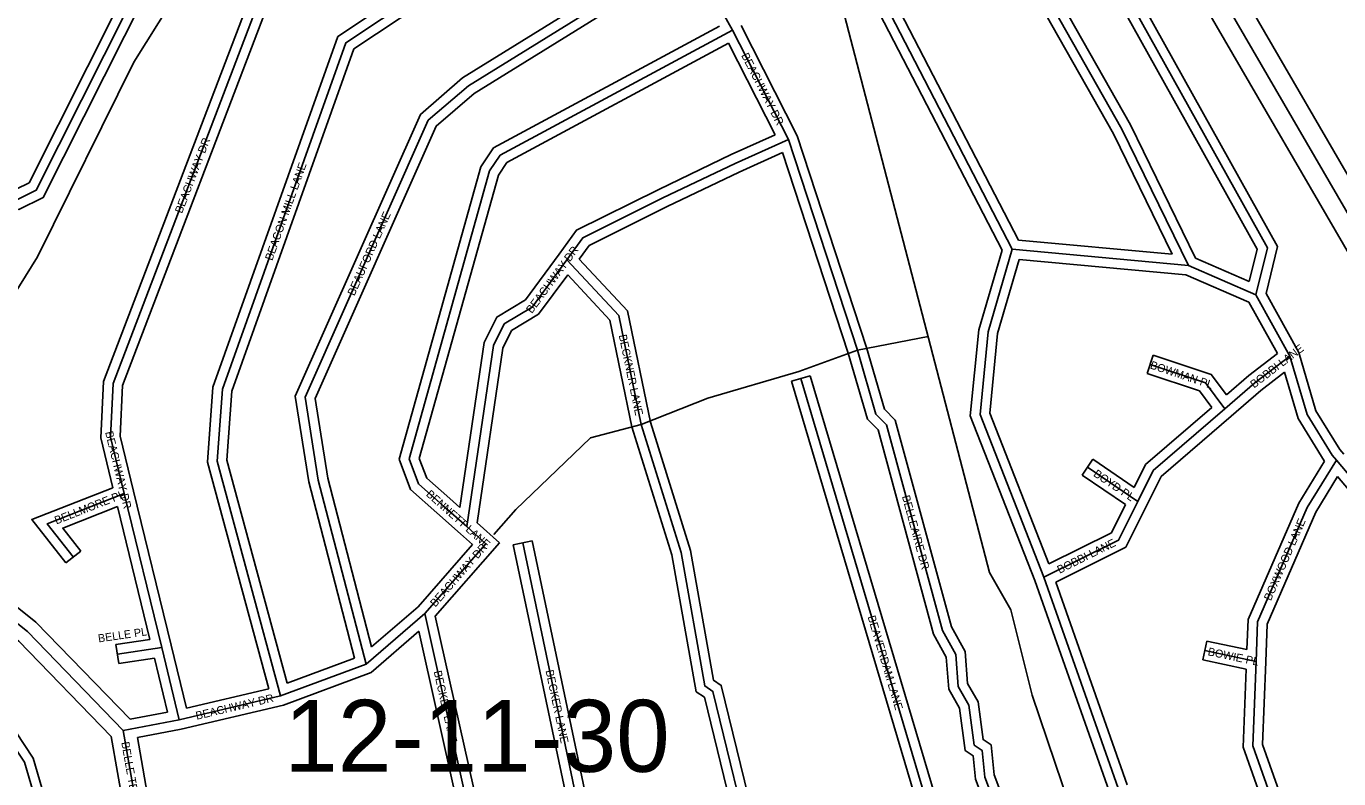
# Model space of a CAD drawing. Extents: x 457167 to 656239, y 1787309 to 1969297.
# Drawn here: x 580059 to 584161, y 1900258 to 1902611 of the extents above; entities that cross this region are included whole.
import ezdxf

# ---------------------------------------------------------------- set-up
doc = ezdxf.new("R2010")
doc.units = 0
for name, color, linetype in [('Level 13', 7, 'Continuous'), ('Level 14', 7, 'Continuous'), ('Level 2', 7, 'Continuous'), ('Level 22', 7, 'Continuous'), ('Level 23', 7, 'Continuous'), ('Level 31', 7, 'Continuous'), ('Level 32', 7, 'Continuous'), ('Level 34', 7, 'Continuous'), ('Level 5', 7, 'Continuous')]:
    doc.layers.add(name, color=color, linetype=linetype)

msp = doc.modelspace()

# ---------------------------------------------------------------- linework, layer by layer
at = {"layer": 'Level 13'}
msp.add_line((584688.869, 1901162.621), (582396.2, 1905115.545), dxfattribs=at)
at = {"layer": 'Level 14'}
for p, q in [((584740.772, 1901192.724), (582448.103, 1905145.647)), ((584636.968, 1901132.518), (582344.298, 1905085.441))]:
    msp.add_line(p, q, dxfattribs=at)
at = {"layer": 'Level 22'}
msp.add_line((580428.56, 1900033.995), (580362.242, 1900409.045), dxfattribs=at)
msp.add_lwpolyline([(580362.242, 1900409.045), (580062.744, 1900718.027), (579859.602, 1900880.267)], dxfattribs=at)
at = {"layer": 'Level 23'}
for p, q in [((580389.425, 1900025.596), (580324.989, 1900390.006)), ((580462.804, 1900070.058), (580406.775, 1900386.923))]:
    msp.add_line(p, q, dxfattribs=at)
for points in [[(580384.317, 1900443.743), (580089.695, 1900747.696), (579884.564, 1900911.523)], [(580324.988, 1900390.006), (580035.794, 1900688.359), (579859.518, 1900829.141)]]:
    msp.add_lwpolyline(points, dxfattribs=at)
at = {"layer": 'Level 31'}
for p, q in [((582266.575, 1902598.675), (582125.284, 1902848.78)), ((582441.067, 1902256.503), (582266.575, 1902598.675)), ((582274.33, 1902181.926), (582441.067, 1902256.503)), ((582656.583, 1901597.52), (582441.067, 1902256.503)), ((582049.027, 1902073.649), (582274.33, 1902181.926)), ((583690.989, 1901862.755), (583140.767, 1901913.656)), ((581639.815, 1901732.647), (581748.524, 1901880.431)), ((583901.593, 1901771.068), (583690.989, 1901862.755)), ((584008.041, 1901578.858), (583901.593, 1901771.068)), ((583898.831, 1901495.433), (584008.041, 1901578.858)), ((583003.924, 1899746.261), (582479.959, 1901509.025)), ((583805.204, 1901414.161), (583898.831, 1901495.433)), ((583533.447, 1901124.871), (583375.647, 1901232.093)), ((584153.338, 1901253.479), (584374.743, 1900990.5)), ((580482.631, 1900668.074), (580365.343, 1901149.412)), ((581362.606, 1901111.381), (581435.916, 1901046.141)), ((581435.916, 1901046.141), (581495.897, 1900992.564)), ((581305.019, 1900774.401), (581495.897, 1900992.564)), ((581820.42, 1899998.442), (581610.676, 1900995.606)), ((583471.604, 1900228.981), (583239.216, 1900887.993)), ((581121.252, 1900616.226), (581305.019, 1900774.401)), ((580482.631, 1900668.074), (580343.971, 1900647.631)), ((580537.49, 1900442.141), (580482.631, 1900668.074)), ((583902.542, 1900624.869), (583742.37, 1900658.637)), ((580854.304, 1900516.767), (581121.252, 1900616.226)), ((580537.49, 1900442.141), (580854.304, 1900516.767)), ((580362.242, 1900409.045), (580537.49, 1900442.141))]:
    msp.add_line(p, q, dxfattribs=at)
for points in [[(582335.899, 1904365.836), (582514.45, 1904471.299), (583937.804, 1901917.545), (583901.593, 1901771.068)], [(583690.989, 1901862.755), (583483.265, 1902288.259), (582826.513, 1903448.117), (582477.519, 1904123.731)], [(583140.767, 1901913.656), (582151.709, 1903824.377), (582151.791, 1903865.832)], [(579794.104, 1902114.238), (580031.815, 1902069.383), (580090.372, 1902097.991), (580656.652, 1903224.119)], [(580854.304, 1900516.767), (580655.499, 1901250.638), (580672.489, 1901475.697), (581057.78, 1902558.929), (581958.997, 1903157.481)], [(581121.252, 1900616.226), (580972.036, 1901191.811), (580930.911, 1901450.443), (581315.758, 1902316.583), (581440.917, 1902424.696), (582125.284, 1902848.78)], [(580330.754, 1901493.124), (580816.27, 1902767.786), (580867.57, 1902824.774)], [(581255.761, 1901258.145), (581507.144, 1902158.012), (581540.624, 1902207.763), (582266.575, 1902598.675)], [(581748.524, 1901880.431), (581798.574, 1901949.059), (582049.027, 1902073.649)], [(583239.216, 1900887.993), (583039.923, 1901396.756), (583065.229, 1901655.256), (583140.767, 1901913.656)], [(581981.167, 1901365.411), (581910.633, 1901706.284), (581748.524, 1901880.431)], [(581435.916, 1901046.141), (581519.718, 1901612.888), (581552.599, 1901680.096), (581639.815, 1901732.647)], [(583237.357, 1899779.255), (583054.859, 1900263.258), (583046.439, 1900346.548), (583021.673, 1900363.325), (583005.069, 1900488.451), (582971.8, 1900546.698), (582963.73, 1900646.716), (582922.23, 1900721.708), (582748.001, 1901363.881), (582714.685, 1901397.401), (582656.583, 1901597.52)], [(584008.041, 1901578.858), (584062.052, 1901396.205), (584140.015, 1901269.505), (584153.338, 1901253.479)], [(583805.204, 1901414.161), (583744.003, 1901496.101), (583571.8, 1901553.529)], [(580365.343, 1901149.412), (580322.148, 1901326.23), (580330.754, 1901493.124)], [(583533.447, 1901124.871), (583581.324, 1901221.143), (583805.204, 1901414.161)], [(582387.155, 1899763.85), (582362.437, 1899964.266), (582337.369, 1899989.043), (582204.914, 1900531.133), (582179.831, 1900547.911), (582105.63, 1900964.792), (581981.167, 1901365.411)], [(581255.761, 1901258.145), (581285.489, 1901179.901), (581362.606, 1901111.381)], [(583902.542, 1900624.869), (583907.234, 1900748.498), (584062.442, 1901105.654), (584153.338, 1901253.479)], [(580365.343, 1901149.412), (580125.114, 1901054.995), (580206.291, 1900951.191)], [(583239.216, 1900887.993), (583472.804, 1901004.262), (583533.447, 1901124.871)], [(581470.657, 1900140.603), (581429.159, 1900215.597), (581305.019, 1900774.401)], [(580543.027, 1898633.378), (580053.642, 1900309.676), (580003.879, 1900384.69), (579687.431, 1900643.528)], [(584550.874, 1899010.497), (584405.606, 1899192.962), (584071.775, 1899853.983), (583891.854, 1900360.887), (583902.542, 1900624.869)]]:
    msp.add_lwpolyline(points, dxfattribs=at)
at = {"layer": 'Level 32'}
for p, q in [((582468.855, 1902268.05), (582293.011, 1902612.874)), ((582399.999, 1902270.999), (582253.788, 1902557.714)), ((582261.706, 1902209.144), (582399.999, 1902270.999)), ((582685.254, 1901606.366), (582468.855, 1902268.049)), ((582286.955, 1902154.708), (582422.909, 1902215.516)), ((582627.914, 1901588.671), (582422.909, 1902215.516)), ((582035.665, 1902100.509), (582261.706, 1902209.144)), ((582062.389, 1902046.787), (582286.955, 1902154.708)), ((583640.623, 1901897.542), (583159.869, 1901942.016)), ((581619.2, 1901755.251), (581724.358, 1901898.208)), ((583880.995, 1901812.756), (583713.1, 1901885.849)), ((583683.431, 1901833.325), (583162.625, 1901881.504)), ((581660.431, 1901710.042), (581751.236, 1901833.486)), ((583880.284, 1901747.626), (583683.431, 1901833.325)), ((584035.879, 1901590.516), (583933.544, 1901775.3)), ((583969.251, 1901586.978), (583880.283, 1901747.626)), ((583562.309, 1901525.069), (583581.29, 1901581.989)), ((583879.874, 1901518.704), (583969.251, 1901586.978)), ((582451.203, 1901500.477), (582508.716, 1901517.573)), ((583025.317, 1899779.582), (582508.716, 1901517.573)), ((583809.919, 1901457.981), (583879.874, 1901518.704)), ((583917.789, 1901472.161), (583991.629, 1901528.566)), ((582967.102, 1899764.853), (582451.203, 1901500.477)), ((583824.869, 1901391.505), (583917.789, 1901472.161)), ((583358.787, 1901207.278), (583392.508, 1901256.906)), ((583521.887, 1901168.997), (583392.508, 1901256.906)), ((583494.826, 1901114.843), (583358.787, 1901207.278)), ((584157.139, 1901202.383), (584338.78, 1900986.633)), ((580511.779, 1900675.176), (580394.491, 1901156.514)), ((580445.692, 1900692.952), (580344.333, 1901108.918)), ((581382.55, 1901133.791), (581414.364, 1901105.48)), ((581342.663, 1901088.97), (581415.973, 1901023.729)), ((581415.931, 1901023.766), (581453.767, 1900989.971)), ((581467.96, 1901057.745), (581538.029, 1900995.156)), ((581283.839, 1900795.754), (581453.767, 1900989.971)), ((581337.599, 1900766.078), (581538.029, 1900995.156)), ((581581.319, 1900989.43), (581640.034, 1901001.78)), ((581779.45, 1900047.478), (581581.319, 1900989.43)), ((581846.52, 1900020.11), (581640.034, 1901001.78)), ((580229.923, 1900969.671), (580182.659, 1900932.709)), ((583443.464, 1900218.574), (583211.095, 1900877.53)), ((583499.747, 1900239.388), (583276.331, 1900872.954)), ((581138.202, 1900670.396), (581283.839, 1900795.754)), ((581136.756, 1900589.986), (581286.602, 1900718.966)), ((580445.692, 1900692.952), (580339.595, 1900677.311)), ((580348.348, 1900617.95), (580339.595, 1900677.311)), ((580559.614, 1900478.173), (580511.784, 1900675.153)), ((583736.182, 1900629.281), (583748.559, 1900687.992)), ((583873.914, 1900661.564), (583748.559, 1900687.992)), ((580459.935, 1900634.401), (580348.348, 1900617.95)), ((580500.884, 1900465.758), (580459.935, 1900634.401)), ((580874.659, 1900556.366), (581085.422, 1900634.891)), ((583871.541, 1900600.744), (583736.182, 1900629.281)), ((580863.016, 1900487.996), (581136.757, 1900589.986)), ((580559.614, 1900478.173), (580817.239, 1900538.858)), ((580384.316, 1900443.743), (580500.884, 1900465.758)), ((580543.717, 1900412.784), (580863.016, 1900487.996)), ((580406.775, 1900386.923), (580543.718, 1900412.785))]:
    msp.add_line(p, q, dxfattribs=at)
for points in [[(582319.358, 1904390.907), (582525.679, 1904512.774), (583969.764, 1901921.822), (583933.544, 1901775.301)], [(582376.878, 1904355.196), (582503.221, 1904429.824), (583905.842, 1901913.267), (583880.996, 1901812.756)], [(583640.623, 1901897.543), (583456.708, 1902274.274), (582800.124, 1903433.837), (582451.228, 1904109.261)], [(583713.099, 1901885.849), (583509.824, 1902302.243), (582852.902, 1903462.398), (582503.813, 1904138.197)], [(583108.6, 1901910.537), (582121.694, 1903817.101), (582121.775, 1903857.911)], [(583159.868, 1901942.016), (582181.724, 1903831.653), (582181.808, 1903873.752)], [(579788.541, 1902084.757), (580036.038, 1902038.056), (580112.63, 1902075.476), (580683.914, 1903211.55)], [(579799.665, 1902143.719), (580027.594, 1902100.71), (580068.114, 1902120.506), (580615.809, 1903209.671)], [(580817.239, 1900538.858), (580625.196, 1901247.763), (580642.876, 1901481.964), (581032.862, 1902578.394), (581919.243, 1903167.091)], [(580874.659, 1900556.366), (580685.802, 1901253.513), (580702.102, 1901469.431), (581082.699, 1902539.463), (581948.188, 1903114.286)], [(580301.039, 1901499.386), (580790.227, 1902783.697), (580845.025, 1902844.566)], [(581085.421, 1900634.891), (580942.634, 1901185.676), (580899.888, 1901454.506), (581291.067, 1902334.9), (581423.1, 1902448.949), (582085.483, 1902859.409)], [(580360.473, 1901486.86), (580842.313, 1902751.876), (580890.115, 1902804.981)], [(581138.202, 1900670.396), (581001.438, 1901197.944), (580961.934, 1901446.38), (581340.449, 1902298.267), (581458.734, 1902400.443), (582114.531, 1902806.821)], [(581224.214, 1901256.713), (581479.552, 1902170.746), (581519.874, 1902230.664), (582225.397, 1902610.573)], [(581287.311, 1901259.575), (581534.734, 1902145.278), (581561.375, 1902184.863), (582253.787, 1902557.715)], [(581724.284, 1901898.109), (581778.653, 1901972.656), (582035.665, 1902100.509)], [(581787.35, 1901882.752), (581818.495, 1901925.461), (582062.389, 1902046.787)], [(583211.095, 1900877.529), (583009.364, 1901392.516), (583035.645, 1901660.977), (583108.6, 1901910.537)], [(582010.25, 1901372.918), (581938.311, 1901720.582), (581787.35, 1901882.752)], [(583255.195, 1900929.456), (583070.481, 1901400.997), (583094.813, 1901649.536), (583162.625, 1901881.504)], [(581952.085, 1901357.902), (581882.955, 1901691.986), (581751.236, 1901833.486)], [(581414.365, 1901105.48), (581490.721, 1901621.886), (581529.538, 1901701.227), (581619.2, 1901755.251)], [(581467.959, 1901057.745), (581548.714, 1901603.89), (581575.659, 1901658.965), (581660.431, 1901710.042)], [(583278.644, 1899754.79), (583084.312, 1900270.175), (583074.876, 1900363.521), (583049.642, 1900380.614), (583034.034, 1900498.224), (583001.166, 1900555.773), (582993.114, 1900655.58), (582950.234, 1900733.063), (582774.877, 1901379.397), (582741.362, 1901413.12), (582685.254, 1901606.366)], [(583196.071, 1899803.717), (583025.405, 1900256.341), (583018, 1900329.576), (582993.704, 1900346.036), (582976.102, 1900478.676), (582942.435, 1900537.624), (582934.348, 1900637.852), (582894.225, 1900710.353), (582721.126, 1901348.363), (582688.009, 1901381.684), (582627.914, 1901588.671)], [(583809.919, 1901457.981), (583762.413, 1901521.586), (583581.29, 1901581.989)], [(584035.879, 1901590.516), (584089.69, 1901408.533), (584164.449, 1901287.043), (584176.408, 1901272.657)], [(583764.43, 1901418.617), (583725.593, 1901470.615), (583562.309, 1901525.069)], [(583991.629, 1901528.566), (584034.414, 1901383.876), (584115.582, 1901251.967), (584116.506, 1901250.855)], [(580329.983, 1901167.748), (580291.96, 1901323.383), (580301.039, 1901499.386)], [(580394.487, 1901156.531), (580352.334, 1901329.077), (580360.473, 1901486.86)], [(583521.887, 1901168.997), (583557.154, 1901239.916), (583764.43, 1901418.617)], [(582351.081, 1899811.258), (582333.937, 1899950.252), (582310.241, 1899973.676), (582178.54, 1900512.681), (582152.534, 1900530.077), (582076.424, 1900957.686), (581952.085, 1901357.902)], [(582414.634, 1899786.146), (582390.936, 1899978.278), (582364.496, 1900004.411), (582231.289, 1900549.585), (582207.129, 1900565.745), (582134.838, 1900971.899), (582010.25, 1901372.918)], [(583560.309, 1901111.512), (583605.493, 1901202.369), (583824.793, 1901391.439)], [(581224.213, 1901256.713), (581260.059, 1901162.364), (581342.679, 1901088.954)], [(581287.312, 1901259.575), (581310.919, 1901197.439), (581382.533, 1901133.808)], [(583873.913, 1900661.564), (583877.469, 1900755.277), (584035.774, 1901119.559), (584116.507, 1901250.855)], [(583932.521, 1900623.731), (583936.999, 1900741.719), (584089.109, 1901091.749), (584157.139, 1901202.384)], [(580329.982, 1901167.748), (580076.701, 1901068.201), (580182.659, 1900932.709)], [(580344.334, 1901108.918), (580173.526, 1901041.788), (580229.923, 1900969.671)], [(583255.194, 1900929.456), (583450.49, 1901026.666), (583494.826, 1901114.843)], [(583276.331, 1900872.954), (583495.119, 1900981.857), (583560.25, 1901111.395)], [(581491.774, 1900164.404), (581457.505, 1900226.333), (581337.599, 1900766.077)], [(581411.309, 1900185.894), (581400.811, 1900204.862), (581286.602, 1900718.966)], [(580564.332, 1898667.456), (580081.162, 1900322.461), (580026.377, 1900405.046), (579728.365, 1900648.804)], [(584546.519, 1899064.134), (584430.996, 1899209.237), (584099.411, 1899865.811), (583922.064, 1900365.462), (583932.519, 1900623.655)], [(584514.824, 1899007.61), (584380.216, 1899176.687), (584044.139, 1899842.156), (583861.644, 1900356.311), (583871.541, 1900600.744)]]:
    msp.add_lwpolyline(points, dxfattribs=at)
at = {"layer": 'Level 5'}
for p, q in [((582656.583, 1901597.52), (582877.418, 1901640.099)), ((582473.327, 1901531.338), (582656.583, 1901597.52)), ((582189.574, 1901448.268), (582473.327, 1901531.338)), ((581981.167, 1901365.411), (582189.574, 1901448.268)), ((581588.947, 1901099.287), (581691.199, 1901197.264)), ((581520.911, 1901021.254), (581588.947, 1901099.287))]:
    msp.add_line(p, q, dxfattribs=at)
for points in [[(579781.515, 1897797.021), (579723.579, 1898180.56), (579657.115, 1898414.045), (579516.342, 1899289.525), (579491.372, 1899306.206), (579491.431, 1899372.887), (579466.46, 1899397.937), (579292.464, 1900423.501), (579292.662, 1900598.566), (580094.305, 1901889.851), (580395.051, 1902498.077), (580770.839, 1903097.903), (580954.725, 1903547.876), (581105.063, 1903839.483), (581221.933, 1903972.737), (581455.514, 1904147.532), (581572.482, 1904389.189)], [(584199.519, 1897567.208), (583667.64, 1899135.033), (583651.069, 1899218.395), (583509.772, 1899610.363), (583202.305, 1900519.354), (583135.871, 1900786.19), (583069.309, 1900902.962), (582596.088, 1902720.814), (582354.858, 1903212.915), (582046.967, 1903738.436), (581572.482, 1904389.189)], [(581691.199, 1901197.264), (581822.756, 1901323.911), (581981.167, 1901365.411)]]:
    msp.add_lwpolyline(points, dxfattribs=at)

# ---------------------------------------------------------------- texts
at = {"layer": 'Level 2'}
msp.add_text('12-11-30', height=225, dxfattribs=at).set_placement((580865.735, 1900279.545))
at = {"layer": 'Level 34'}
for s, height, rotation, p in [('BEACHWAY DR', 24.99916, 297.019103, (582292.895, 1902519.551)), ('BEACHWAY DR', 25, 69.147389, (580546.178, 1902023.579)), ('BEACON MILL LANE', 25, 70.419269, (580828.146, 1901876.027)), ('BEAUFORD LANE', 24.99916, 66.042392, (581084.689, 1901765.759)), ('BEACHWAY DR', 25, 53.661247, (581639.29, 1901710.842)), ('BECKNER LANE', 25, 281.690058, (581910.685, 1901644.35)), ('BOBBI LANE', 25, 37.374942, (583896.073, 1901477.598)), ('BOWMAN PL', 25, 341.556403, (583569.243, 1901541.206)), ('BEACHWAY DR', 25, 283.727311, (580305.594, 1901341.331)), ('BOYD PL', 25, 325.804808, (583392.033, 1901205.846)), ('BELLMORE PL', 25, 21.455742, (580153.506, 1901052.724)), ('BENNETT LANE', 25, 318.333325, (581306.602, 1901144.487)), ('BELLEAIRE DR', 25, 285.178994, (582795.589, 1901140.745)), ('BOXWOOD LANE', 25, 66.510961, (583948.66, 1900812.471)), ('BEACHWAY DR', 25, 48.8151, (581337.69, 1900792.764)), ('BOBBI LANE', 25, 26.461267, (583288.41, 1900898.517)), ('BEAVERDAM LANE', 25, 286.5535, (582688.282, 1900764.303)), ('BELLE PL', 25, 8.38665, (580285.614, 1900683.986)), ('BOWIE PL', 25, 348.09475, (583750.074, 1900644.239)), ('BECKET LANE', 25, 282.524431, (581332.449, 1900593.291)), ('BECKER LANE', 25, 281.877881, (581682.02, 1900595.701)), ('BEACHWAY DR', 25, 13.25425, (580592.077, 1900442.157)), ('BELLE TERRE PKWY', 24.99916, 280.027161, (580356.194, 1900371.465))]:
    msp.add_text(s, height=height, rotation=rotation, dxfattribs=at).set_placement(p)

doc.saveas('drawing.dxf')
